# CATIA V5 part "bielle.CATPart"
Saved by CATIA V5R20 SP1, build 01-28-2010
Part number: Part1
Bounding box of the stored display mesh (mm): x 48 to 87, y 0 to 30, z 28.093 to 41.907
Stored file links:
  E:\EDELI\gcausse\Edeli_2012_685_gcausse\bielle.CATPart
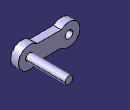
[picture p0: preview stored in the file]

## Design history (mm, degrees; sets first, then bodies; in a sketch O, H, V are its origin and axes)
Parameters
  long = 0.025
  diamtrou = 0.005
Body1 (main body)
  Sketch1 on zx-plane, origin (0, 0, 0), H (-1, 0, 0), V (0, 0, 1)
    line L1 (-59.899, 40) -> (-75.101, 40)
    line L2 (-59.899, 30) -> (-75.101, 30)
    arc A1 centre (-55, 35) radius 7 from (-59.899, 40) to (-59.899, 30) cw
    point P5 (-55, 35)
    point P6 (-50.101, 30)
    arc A2 centre (-80, 35) radius 7 from (-75.101, 40) to (-75.101, 30) ccw
    point P7 (-80, 35)
    circle A3 centre (-55, 35) radius 2.5
    distance P7 L1 = 5
    distance P5 L2 = 5
    distance L2 L1 = 10
    radius A1 = 7
    radius A2 = 7
    distance P5 P7 = 25 {= long}
    radius A3 = 2.5
    horizontal: L1 H, L2 H
    coincidence: A1 P6, P6 L2
  Pad1: profile Sketch1, direction (0, 1, 0), length 5
  Sketch2 on end face of Pad1, origin (0, 5, 0), H (-1, 0, 0), V (0, 0, 1)
    circle A1 centre (-80, 35) radius 2.5
    reference projected arc E1 centre (-80, 35) radius 7 from (-75.101, 40) to (-75.101, 30) ccw from edge [face of Pad1 from Sketch1.A2 | end face of Pad1]
    reference projected arc E2 centre (-80, 35) radius 7 from (-75.101, 40) to (-75.101, 30) ccw from edge [face of Pad1 from Sketch1.A2 | end face of Pad1]
    radius A1 = 2.5
    radius E2 = 7 (reference)
    concentricity: A1 E1
  Pad2: profile Sketch2, direction (0, 1, 0), length 25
